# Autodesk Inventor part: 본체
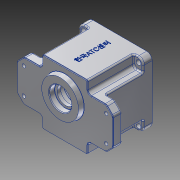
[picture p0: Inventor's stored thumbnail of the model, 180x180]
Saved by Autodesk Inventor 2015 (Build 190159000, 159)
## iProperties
Created: 2016-02
Part Number: 본체
Material: 알루미늄 6061
Document SubType Name: Modeling
Designer: Administrator
Density: 2.7 g/cm^3
Appearance: 알루미늄 - 평지
Mass: 879.657 g
Surface Area: 763.885 cm^2
Volume: 325.799 cm^3
Author: Administrator
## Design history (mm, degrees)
sketch "스케치1"
  geometry: L1 (47, -47)-(-47, -47); L2 (-47, -47)-(-47, 47); L3 (-47, 47)-(47, 47); L4 (47, 47)-(47, -47); L5 (47, -47)-(-47, 47); L6 (-47, -47)-(47, 47); 1 further point
  constraints: 12 end point, 2 midpoint, 2 parallel, 1 horizontal, 1 perpendicular
  dimensions: "d0" = 94 distance of L2.end L3.end; "d1" = 94 distance of L1.end L2.end
extrude "돌출1" new body sketch "스케치1" distance "d2" = 80; taper "d3" = 0 deg
sketch "스케치2"
  geometry: L1 (47, 47)-(-47, 47) reference; L2 (-47, 47)-(-47, -47) reference; L3 (-47, -47)-(47, -47) reference; L4 (47, -47)-(47, 47) reference; L5 (-47, 47)-(-33, 47); L6 (-33, 47)-(-33, 30); L7 (-33, 30)-(-47, 30); L8 (-47, 30)-(-47, 47); L9 (47, 47)-(33, 47); L10 (33, 47)-(33, 30); L11 (33, 30)-(47, 30); L12 (47, 30)-(47, 47); L13 (47, -47)-(33, -47); L14 (33, -47)-(33, -30); L15 (33, -30)-(47, -30); L16 (47, -30)-(47, -47); L17 (-47, -47)-(-33, -47); L18 (-33, -47)-(-33, -30); L19 (-33, -30)-(-47, -30); L20 (-47, -30)-(-47, -47); 1 further point
  constraints: 32 end point, 8 parallel, 4 horizontal, 4 perpendicular, 4 point on line
  dimensions: "d4" = 60 distance between parallel lines of L19 L7; "d5" = 30 distance from line of L7 point (0, 0) (= 0.5 x d4); "d6" = 66 distance between parallel lines of L10 L6; "d7" = 33 distance from line of point (0, 0) L10 (= 0.5 x d6)
extrude "돌출2" cut sketch "스케치2" distance "d8" = 67; taper "d9" = 0 deg
fillet "모깎기1" dims "d10" = 8
sketch "스케치3"
  geometry: C1 r 3.5 at (-40, 40); C2 r 3.5 at (40, 40); C3 r 3.5 at (40, -40); C4 r 3.5 at (-40, -40); A1 r 8 centre (-39, 39) between (-39, 47) and (-47, 39) reference; A2 r 8 centre (39, 39) between (47, 39) and (39, 47) reference; A3 r 8 centre (39, -39) between (39, -47) and (47, -39) reference; A4 r 8 centre (-39, -39) between (-47, -39) and (-39, -47) reference; 1 further point
  constraints: 4 centre point
  dimensions: "d11" = 78 distance of A2.centre A1.centre (derived); "d12" = 78 distance of A3.centre A2.centre (derived); "d13" = 7 diameter of C1; "d14" = 7 diameter of C2; "d15" = 7 diameter of C3; "d16" = 7 diameter of C4; "d17" = 80 distance of C2.centre C1.centre; "d18" = 80 distance of C3.centre C2.centre; "d19" = 40 horizontal distance of point (0, 0) C2.centre (= 0.5 x d17); "d20" = 40 horizontal distance of C2.centre point (0, 0) (= 0.5 x d18); "d21" = 40 horizontal distance of C3.centre point (0, 0) (= d19); "d22" = 40 horizontal distance of point (0, 0) C1.centre; "d23" = 40 horizontal distance of C4.centre point (0, 0) (= d22); "d24" = 40 horizontal distance of point (0, 0) C4.centre (= d21)
extrude "돌출3" cut sketch "스케치3" stored distance "d25" = 67; taper "d26" = 0 deg
sketch "스케치4"
  geometry: L1 (33, -47)-(33, -30) reference; L2 (33, -30)-(47, -30) reference; L3 (47, -30)-(47, 30) reference; L4 (47, 30)-(33, 30) reference; L5 (33, 30)-(33, 47) reference; L6 (33, 47)-(-33, 47) reference; L7 (-33, 47)-(-33, 30) reference; L8 (-33, 30)-(-47, 30) reference; L9 (-47, 30)-(-47, -30) reference; L10 (-47, -30)-(-33, -30) reference; L11 (-33, -30)-(-33, -47) reference; L12 (-33, -47)-(33, -47) reference; L13 (-47, 30)-(-70, 30); L14 (-70, 30)-(-70, -30); L15 (-70, -30)-(-47, -30); L16 (-47, -30)-(-47, 30); L17 (47, 30)-(70, 30); L18 (70, 30)-(70, -30); L19 (70, -30)-(47, -30); L20 (47, -30)-(47, 30); 1 further point
  constraints: 16 end point, 4 parallel, 2 horizontal, 2 perpendicular
  dimensions: "d27" = 140 distance between parallel lines of L18 L14; "d28" = 94 distance between parallel lines of L3 L9 (derived); "d29" = 23 distance between parallel lines of L9 L14 (= -0.5 x d28 + 0.5 x d27)
extrude "돌출4" join sketch "스케치4" distance "d30" = 13; taper "d31" = 0 deg
sketch "스케치6"
  geometry: L1 (60, -19)-(-60, -19); L2 (-60, -19)-(-60, 19); L3 (-60, 19)-(60, 19); L4 (60, 19)-(60, -19); L5 (60, -19)-(-60, 19); L6 (-60, -19)-(60, 19); 5 further points
  constraints: 12 end point, 4 coincident, 2 midpoint, 2 parallel, 1 horizontal, 1 perpendicular
  dimensions: "d34" = 38 distance between parallel lines of L3 L1; "d35" = 120 distance between parallel lines of L4 L2
hole "구멍1" sketch "스케치6" at (-60, -19), (-60, 19), (60, 19), (60, -19) diameter "d36" = 5; stored, may be unused: countersink angle "d40" = 90 deg, drill point angle "d42" = 0 deg; dims "d37" = 6, "d38" = 9, "d39" = 4, "d41" = 13
chamfer "모따기1" distance "d43" = 10; stored, may be unused: second distance "d44" = 2, angle "d45" = 45 deg
sketch "스케치7"
  geometry: C1 r 28 at (0, 11); 1 further point
  constraints: 1 centre point, 1 vertical alignment
  dimensions: "d46" = 56 diameter of C1; "d47" = 11 distance of point (0, 0) C1.centre
extrude "돌출5" join sketch "스케치7" distance "d48" = 7; taper "d49" = -10 deg
fillet "모깎기2" dims "d50" = 5
sketch "스케치8"
  geometry: C1 r 43 at (0, 0); 1 further point
  constraints: 1 centre point, 1 coincident
  dimensions: "d51" = 86 diameter of C1
extrude "돌출6" cut sketch "스케치8" distance "d52" = 9; taper "d53" = 0 deg
sketch "스케치9"
  geometry: A1 r 40 centre (0, 0) between (-39.148, -8.214) and (39.148, -8.214); A2 r 36 centre (0, 0) between (36, 0) and (-36, 0); A3 r 4 centre (36, 0) between (35.852, 3.997) and (35.852, -3.997); A4 r 4 centre (-36, 0) between (-35.852, -3.997) and (-35.852, 3.997); A5 r 3.5 centre (35.722, -7.495) between (39.148, -8.214) and (35.778, -3.995); A6 r 3.5 centre (35.722, 7.495) between (35.852, 3.997) and (39.148, 8.214); A7 r 3.5 centre (-35.722, -7.495) between (-35.852, -3.997) and (-39.148, -8.214); A8 r 3.5 centre (-35.722, 7.495) between (-39.148, 8.214) and (-35.852, 3.997); A9 r 40 centre (0, 0) between (-40, 0) and (-39.148, -8.214); A10 r 40 centre (0, 0) between (-39.148, 8.214) and (-40, 0); A11 r 4 centre (-36, 0) between (-40, 0) and (-35.852, -3.997); A12 r 4 centre (-36, 0) between (-35.852, 3.997) and (-40, 0); A13 r 40 centre (0, 0) between (39.148, -8.214) and (39.148, 8.214); A14 r 40 centre (0, 0) between (39.148, 8.214) and (-39.148, 8.214); A15 r 4 centre (36, 0) between (40, 0) and (35.852, 3.997); A16 r 4 centre (36, 0) between (35.852, -3.997) and (40, 0); 1 further point
  constraints: 38 point on circle, 16 centre point, 8 tangent, 2 coincident, 2 horizontal alignment
  dimensions: "d54" = 80 diameter of A1; "d55" = 36 radius of A2; "d56" = 4 radius of A3; "d57" = 4 radius of A4; "d58" = 3.5 radius of A5; "d59" = 3.5 radius of A6; "d60" = 3.5 radius of A8; "d61" = 3.5 radius of A7
extrude "돌출7" cut sketch "스케치9" distance "d62" = 62; taper "d63" = 0 deg
fillet "모깎기3" dims "d67" = 2
sketch "스케치11"
  geometry: L1 (-33, 45)-(-33, 35) reference; L2 (-38, 30)-(-57.929, 30) reference; L3 (-68.536, 21.464)-(-61.464, 28.536) reference; L4 (-70, 17.929)-(-70, -17.929) reference; L5 (-61.464, -28.536)-(-68.536, -21.464) reference; L6 (-57.929, -30)-(-38, -30) reference; L7 (-33, -35)-(-33, -45) reference; L8 (-31, -47)-(31, -47) reference; L9 (33, -45)-(33, -35) reference; L10 (38, -30)-(57.929, -30) reference; L11 (68.536, -21.464)-(61.464, -28.536) reference; L12 (70, -17.929)-(70, 17.929) reference; L13 (61.464, 28.536)-(68.536, 21.464) reference; L14 (57.929, 30)-(38, 30) reference; L15 (33, 35)-(33, 45) reference; L16 (31, 47)-(-31, 47) reference; L17 (31, -46)-(-31, -46); L18 (-32, -45)-(-32, -35); L19 (-38, -29)-(-57.929, -29); L20 (-60.757, -27.828)-(-67.828, -20.757); L21 (-69, -17.929)-(-69, 17.929); L22 (-67.828, 20.757)-(-60.757, 27.828); L23 (-57.929, 29)-(-38, 29); L24 (-32, 35)-(-32, 45); L25 (-31, 46)-(31, 46); L26 (32, 45)-(32, 35); L27 (38, 29)-(57.929, 29); L28 (60.757, 27.828)-(67.828, 20.757); L29 (69, 17.929)-(69, -17.929); L30 (67.828, -20.757)-(60.757, -27.828); L31 (57.929, -29)-(38, -29); L32 (32, -35)-(32, -45); C1 r 28 at (0, 11) reference; C2 r 2.5 at (60, -19) reference; C3 r 2.5 at (-60, 19) reference; C4 r 2.5 at (-60, -19) reference; C5 r 2.5 at (60, 19) reference; A1 r 2 centre (-31, 45) between (-31, 47) and (-33, 45) reference; A2 r 5 centre (-38, 35) between (-38, 30) and (-33, 35) reference; A3 r 5 centre (-57.929, 25) between (-57.929, 30) and (-61.464, 28.536) reference; A4 r 5 centre (-65, 17.929) between (-68.536, 21.464) and (-70, 17.929) reference; A5 r 5 centre (-65, -17.929) between (-70, -17.929) and (-68.536, -21.464) reference; A6 r 5 centre (-57.929, -25) between (-61.464, -28.536) and (-57.929, -30) reference; A7 r 5 centre (-38, -35) between (-33, -35) and (-38, -30) reference; A8 r 2 centre (-31, -45) between (-33, -45) and (-31, -47) reference; A9 r 2 centre (31, -45) between (31, -47) and (33, -45) reference; A10 r 5 centre (38, -35) between (38, -30) and (33, -35) reference; A11 r 5 centre (57.929, -25) between (57.929, -30) and (61.464, -28.536) reference; A12 r 5 centre (65, -17.929) between (68.536, -21.464) and (70, -17.929) reference; A13 r 5 centre (65, 17.929) between (70, 17.929) and (68.536, 21.464) reference; A14 r 5 centre (57.929, 25) between (61.464, 28.536) and (57.929, 30) reference; A15 r 5 centre (38, 35) between (33, 35) and (38, 30) reference; A16 r 2 centre (31, 45) between (33, 45) and (31, 47) reference; A17 r 1 centre (-31, -45) between (-32, -45) and (-31, -46); A18 r 6 centre (-38, -35) between (-32, -35) and (-38, -29); A19 r 4 centre (-57.929, -25) between (-60.757, -27.828) and (-57.929, -29); A20 r 4 centre (-65, -17.929) between (-69, -17.929) and (-67.828, -20.757); A21 r 4 centre (-65, 17.929) between (-67.828, 20.757) and (-69, 17.929); A22 r 4 centre (-57.929, 25) between (-57.929, 29) and (-60.757, 27.828); A23 r 6 centre (-38, 35) between (-38, 29) and (-32, 35); A24 r 1 centre (-31, 45) between (-31, 46) and (-32, 45); A25 r 1 centre (31, 45) between (32, 45) and (31, 46); A26 r 6 centre (38, 35) between (32, 35) and (38, 29); A27 r 4 centre (57.929, 25) between (60.757, 27.828) and (57.929, 29); A28 r 4 centre (65, 17.929) between (69, 17.929) and (67.828, 20.757); A29 r 4 centre (65, -17.929) between (67.828, -20.757) and (69, -17.929); A30 r 4 centre (57.929, -25) between (57.929, -29) and (60.757, -27.828); A31 r 6 centre (38, -35) between (38, -29) and (32, -35); A32 r 1 centre (31, -45) between (31, -46) and (32, -45); 1 further point
  constraints: 32 end point, 32 point on circle, 16 centre point, 31 other
  dimensions: "d68" = 1 distance between parallel lines of L16 L25
extrude "돌출9" cut sketch "스케치11" distance "d69" = 1; taper "d70" = 0 deg
sketch "스케치12"
  geometry: A1 r 21 centre (0, -11) between (-12.163, 6.119) and (12.163, 6.119); A2 r 15 centre (0, 20) between (11.584, 10.47) and (-11.584, 10.47); A3 r 3 centre (13.901, 8.565) between (11.584, 10.47) and (12.163, 6.119); A4 r 3 centre (-13.901, 8.565) between (-12.163, 6.119) and (-11.584, 10.47); 1 further point
  constraints: 8 point on circle, 4 centre point, 4 tangent, 2 vertical alignment, 1 equal radius
  dimensions: "d71" = 21 radius of A1; "d72" = 11 distance of point (0, 0) A1.centre; "d73" = 15 radius of A2; "d74" = 20 distance of A2.centre point (0, 0); "d75" = 3 radius of A3
extrude "돌출10" join sketch "스케치12" distance "d76" = 7; taper "d77" = 0 deg
hole "구멍3" diameter "d91" = 25; stored, may be unused: countersink angle "d95" = 90 deg, drill point angle "d97" = 0 deg; dims "d89" = 10, "d90" = 10, "d92" = 6, "d93" = 35, "d94" = 10, "d96" = 8
sketch "스케치13"
  geometry: C1 r 12.5 at (0, 0) reference; C2 r 16 at (0, 0); 1 further point
  constraints: 1 centre point, 1 coincident
  dimensions: "d98" = 16 radius of C2
extrude "돌출11" cut sketch "스케치13" distance "d99" = 8; taper "d100" = 0 deg
fillet "모깎기6" dims "d101" = 0.3
chamfer "모따기2" distance "d102" = 1; stored, may be unused: second distance "d103" = 2, angle "d104" = 45 deg
sketch "스케치14"
  geometry: A1 r 4 centre (36, 0) between (35.852, 3.997) and (35.852, -3.997) reference; A2 r 4 centre (-36, 0) between (-35.852, -3.997) and (-35.852, 3.997) reference; 3 further points
  constraints: 2 coincident
hole "구멍4" sketch "스케치14" at (36, 0), (-36, 0) diameter "d105" = 3.242; stored, may be unused: countersink angle "d109" = 90 deg, drill point angle "d111" = 118 deg; dims "d106" = 7, "d107" = 35, "d108" = 10, "d110" = 9
fillet "모깎기7" dims "d112" = 2
sketch "스케치15" dims "d0" = 94, "d1" = 94
  geometry: L1 (78, 0)-(0, 0) reference; 3 further points
  constraints: 1 midpoint, 1 vertical alignment, 1 other
  dimensions: "d113" = 40 distance of point (39, 0) point (39, -40)
feature "엠보싱1" sketch "스케치15" dims "d0" = 94, "d1" = 94, "d4" = 60, "d5" = 30 (= 0.5 x d4), "d6" = 66, "d7" = 33 (= 0.5 x d6), "d114" = 0.5, "d115" = 0
fillet "모깎기8" dims "d116" = 0.3
sketch "Sketch18"
  geometry: C1 r 18.5 at (0, -11) reference; C2 r 11 at (0, 20); A1 r 3 centre (13.901, 8.565) between (11.584, 10.47) and (12.163, 6.119) reference; A2 r 15 centre (0, 20) between (11.584, 10.47) and (-11.584, 10.47) reference; A3 r 3 centre (-13.901, 8.565) between (-12.163, 6.119) and (-11.584, 10.47) reference; A4 r 21 centre (0, -11) between (-12.163, 6.119) and (12.163, 6.119) reference; 1 further point
  constraints: 1 centre point, 1 coincident
  dimensions: "d121" = 22 diameter of C2
extrude "Extrusion13" cut sketch "Sketch18" distance "d122" = 7; taper "d123" = 0 deg
sketch "Sketch19"
  geometry: C1 r 11 at (0, 0) reference; C2 r 9.5 at (0, 0); 1 further point
  constraints: 1 centre point, 1 coincident
  dimensions: "d124" = 19 diameter of C2
extrude "Extrusion14" cut sketch "Sketch19" distance "d125" = 1; taper "d126" = 0 deg
fillet "Fillet9" dims "d127" = 2
node "솔리드1"
node "투영된 루프1"
node "투영된 루프3"
node "Projected Loop6"
node "Projected Loop7"
